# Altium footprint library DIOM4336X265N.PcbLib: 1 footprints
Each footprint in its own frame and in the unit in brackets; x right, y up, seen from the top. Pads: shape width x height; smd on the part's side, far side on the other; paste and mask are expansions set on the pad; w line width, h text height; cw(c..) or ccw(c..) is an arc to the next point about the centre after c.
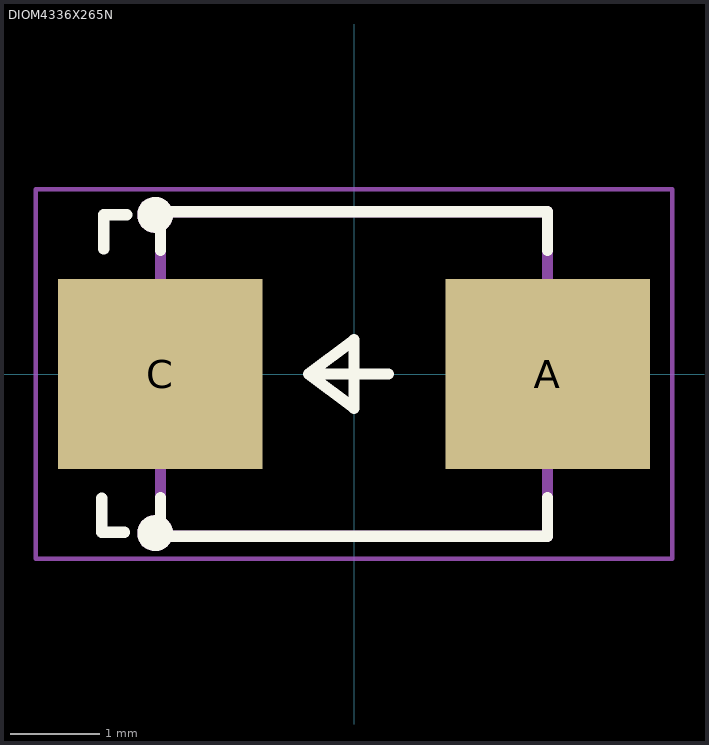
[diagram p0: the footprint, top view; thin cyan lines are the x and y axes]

## DIOM4336X265N [mm]
height 2.65
pads (2):
  rect 2.28x2.12 smd: A(2.165,0) C(-2.165,0)
Top Overlay:
  circle w0.2: c-2.222,1.778 r0.1
  circle w0.2: c-2.222,-1.778 r0.1
  lines w0.127: -2.818,-1.387 -2.818,-1.768 -2.564,-1.768 ; -2.794,1.397 -2.794,1.778 -2.54,1.778 ; -2.163,-1.38 -2.163,-1.813 2.163,-1.813 2.163,-1.38 ; -2.163,1.38 -2.163,1.813 2.163,1.813 2.163,1.38 ; 0.381,0 -0.508,0 ; -0.508,0 0,0.381 0,-0.381 -0.508,0
Mechanical 13:
  circle w0.2: c-2.222,1.778 r0.1
  circle w0.2: c-2.222,-1.778 r0.1
  lines w0.127: -2.163,-1.813 -2.163,1.813 2.163,1.813 2.163,-1.813 -2.163,-1.813
Mechanical 15:
  lines w0.05: -3.555,-2.063 -3.555,2.063 3.555,2.063 3.555,-2.063 -3.555,-2.063
3D body "step_temp.STEP": height 2.65, standoff 0, extent -2.675,-1.813 2.675,1.813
